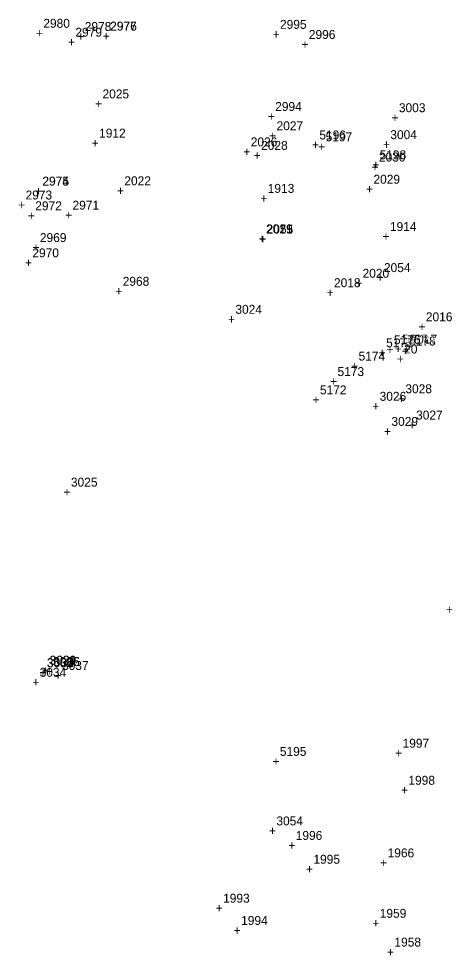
# Model space of a CAD drawing. Extents: x 1036751 to 1042192, y 772604 to 785439.
# Drawn here: x 1040862.7 to 1040984, y 774764.4 to 775026.4 of the extents above; entities that cross this region are included whole.
import ezdxf

# ---------------------------------------------------------------- set-up
doc = ezdxf.new("R2010")
doc.units = 0
for name, color, linetype in [('S_Control_Geodetic_ControlPoint', 7, 'Continuous'), ('S_Curb_Type_3', 7, 'Continuous'), ('S_Drainage_CB', 7, 'Continuous'), ('S_Drainage_Culvert_Top', 7, 'Continuous'), ('S_Drainage_Invert', 7, 'Continuous'), ('S_Drainage_Sump', 7, 'Continuous'), ('S_Fencing_Picket', 7, 'Continuous'), ('S_Ground_LevelString', 7, 'Continuous'), ('S_Property_IronPipeFound', 7, 'Continuous'), ('S_Property_Light', 7, 'Continuous'), ('S_Roadway_Centerline', 7, 'Continuous'), ('S_Roadway_Edge_Pavement', 7, 'Continuous'), ('S_Roadway_Edge_TW', 7, 'Continuous'), ('S_Traffic_Sign_DoublePost', 7, 'Continuous'), ('S_Traffic_Sign_SinglePost', 7, 'Continuous'), ('S_Trees_Decid_Pay', 7, 'Continuous'), ('S_Utilities_GuyWire3', 7, 'Continuous'), ('S_Utilities_Pole_Power', 7, 'Continuous')]:
    doc.layers.add(name, color=color, linetype=linetype)

msp = doc.modelspace()

# ---------------------------------------------------------------- texts
at = {"layer": 'S_Control_Geodetic_ControlPoint'}
for s, p in [('20', (1040970.51, 774932.71)), ('20', (1040970.51, 774932.71)), ('20', (1040970.51, 774932.71)), ('20', (1040970.51, 774932.71)), ('20', (1040970.51, 774932.71)), ('20', (1040970.51, 774932.71)), ('20', (1040970.51, 774932.71)), ('20', (1040970.51, 774932.71)), ('20', (1040970.51, 774932.71)), ('20', (1040970.51, 774932.71)), ('+', (1040968.45, 774929.96)), ('+', (1040968.45, 774929.96)), ('+', (1040968.45, 774929.96)), ('+', (1040968.45, 774929.96)), ('+', (1040968.45, 774929.96)), ('+', (1040968.45, 774929.96)), ('+', (1040968.45, 774929.96)), ('+', (1040968.45, 774929.96)), ('+', (1040968.45, 774929.96)), ('+', (1040968.45, 774929.96))]:
    msp.add_text(s, height=2.5, dxfattribs=at).set_placement(p)
at = {"layer": 'S_Curb_Type_3'}
for s, p in [('5196', (1040946.79, 774992.59)), ('5197', (1040948.54, 774992.08)), ('+', (1040944.73, 774989.84)), ('+', (1040946.48, 774989.33)), ('5198', (1040963.65, 774987.05)), ('+', (1040961.59, 774984.3)), ('5176', (1040967.65, 774935.32)), ('5177', (1040969.93, 774935.52)), ('5178', (1040971.91, 774934.94)), ('5175', (1040965.46, 774934.47)), ('+', (1040965.59, 774932.57)), ('+', (1040967.87, 774932.77)), ('5174', (1040957.76, 774930.74)), ('+', (1040963.4, 774931.72)), ('+', (1040969.85, 774932.19)), ('+', (1040955.7, 774927.99)), ('5173', (1040951.87, 774926.4)), ('+', (1040949.81, 774923.65)), ('5172', (1040946.95, 774921.28)), ('+', (1040944.89, 774918.53)), ('+', (1040982.18, 774859.93)), ('5195', (1040935.74, 774820.15)), ('+', (1040933.68, 774817.4))]:
    msp.add_text(s, height=2.5, dxfattribs=at).set_placement(p)
at = {"layer": 'S_Drainage_CB'}
for s, p in [('3030', (1040871.32, 774845.69)), ('+', (1040869.26, 774842.94))]:
    msp.add_text(s, height=2.5, dxfattribs=at).set_placement(p)
at = {"layer": 'S_Drainage_Culvert_Top'}
for s, p in [('2976', (1040888.3, 775023.03)), ('+', (1040886.24, 775020.28)), ('2975', (1040869.34, 774979.67)), ('+', (1040867.28, 774976.92)), ('3033', (1040870.57, 774844.91)), ('3036', (1040872.34, 774845.26)), ('3037', (1040874.81, 774844.18)), ('3034', (1040868.55, 774842.27)), ('+', (1040868.51, 774842.16)), ('+', (1040870.28, 774842.51)), ('+', (1040872.75, 774841.43)), ('+', (1040866.49, 774839.52))]:
    msp.add_text(s, height=2.5, dxfattribs=at).set_placement(p)
at = {"layer": 'S_Drainage_Invert'}
for s, p in [('2977', (1040888.25, 775023.06)), ('+', (1040886.19, 775020.31)), ('2974', (1040869.3, 774979.67)), ('+', (1040867.23, 774976.92)), ('3032', (1040870.59, 774844.98)), ('3035', (1040872.33, 774845.27)), ('+', (1040868.53, 774842.23)), ('+', (1040870.27, 774842.52))]:
    msp.add_text(s, height=2.5, dxfattribs=at).set_placement(p)
at = {"layer": 'S_Drainage_Sump'}
for s, p in [('3031', (1040871.32, 774845.64)), ('+', (1040869.25, 774842.89))]:
    msp.add_text(s, height=2.5, dxfattribs=at).set_placement(p)
at = {"layer": 'S_Fencing_Picket'}
for s, p in [('2980', (1040869.57, 775023.82)), ('2995', (1040935.78, 775023.53)), ('2979', (1040878.55, 775021.33)), ('+', (1040867.5, 775021.07)), ('+', (1040933.72, 775020.78)), ('2996', (1040943.85, 775020.7)), ('+', (1040876.49, 775018.58)), ('+', (1040941.79, 775017.95))]:
    msp.add_text(s, height=2.5, dxfattribs=at).set_placement(p)
at = {"layer": 'S_Ground_LevelString'}
for s, p in [('2055', (1040932.04, 774966.25)), ('+', (1040929.98, 774963.5)), ('2054', (1040964.86, 774955.48)), ('+', (1040962.8, 774952.73))]:
    msp.add_text(s, height=2.5, dxfattribs=at).set_placement(p)
at = {"layer": 'S_Property_IronPipeFound'}
for s, p in [('2978', (1040881.17, 775022.94)), ('+', (1040879.11, 775020.19)), ('3024', (1040923.3, 774943.81)), ('+', (1040921.24, 774941.06)), ('3025', (1040877.3, 774895.47)), ('+', (1040875.24, 774892.72))]:
    msp.add_text(s, height=2.5, dxfattribs=at).set_placement(p)
at = {"layer": 'S_Property_Light'}
for s, p in [('3026', (1040963.65, 774919.48)), ('+', (1040961.59, 774916.73)), ('3027', (1040973.85, 774914.24)), ('+', (1040971.79, 774911.49))]:
    msp.add_text(s, height=2.5, dxfattribs=at).set_placement(p)
at = {"layer": 'S_Roadway_Centerline'}
for s, p in [('1912', (1040885.18, 774993.11)), ('+', (1040883.12, 774990.36)), ('1913', (1040932.35, 774977.65)), ('+', (1040930.29, 774974.9)), ('1914', (1040966.53, 774966.96)), ('+', (1040964.47, 774964.21)), ('1966', (1040965.88, 774791.76)), ('+', (1040963.82, 774789.01))]:
    msp.add_text(s, height=2.5, dxfattribs=at).set_placement(p)
at = {"layer": 'S_Roadway_Edge_Pavement'}
for s, p in [('2025', (1040886.13, 775004.07)), ('+', (1040884.07, 775001.32)), ('2027', (1040934.82, 774995.16)), ('2026', (1040927.6, 774990.65)), ('+', (1040932.76, 774992.41)), ('+', (1040925.54, 774987.9)), ('2030', (1040963.45, 774986.4)), ('+', (1040961.39, 774983.65)), ('2022', (1040892.24, 774979.77)), ('+', (1040890.17, 774977.02)), ('2019', (1040931.88, 774966.33)), ('+', (1040929.82, 774963.58)), ('2018', (1040950.89, 774951.26)), ('+', (1040948.83, 774948.51)), ('2017', (1040972.29, 774935.48)), ('+', (1040970.23, 774932.73)), ('1997', (1040970.06, 774822.44)), ('+', (1040968, 774819.69)), ('1996', (1040940.19, 774796.65)), ('+', (1040938.13, 774793.9)), ('1993', (1040919.87, 774779.08)), ('+', (1040917.81, 774776.33)), ('1958', (1040967.79, 774766.81)), ('+', (1040965.73, 774764.06))]:
    msp.add_text(s, height=2.5, dxfattribs=at).set_placement(p)
at = {"layer": 'S_Roadway_Edge_TW'}
for s, p in [('2028', (1040930.5, 774989.67)), ('+', (1040928.44, 774986.92)), ('2029', (1040961.92, 774980.2)), ('+', (1040959.86, 774977.45)), ('2021', (1040931.88, 774966.35)), ('+', (1040929.82, 774963.6)), ('2020', (1040958.88, 774953.89)), ('+', (1040956.82, 774951.14)), ('2016', (1040976.58, 774941.72)), ('+', (1040974.52, 774938.97)), ('1998', (1040971.7, 774812.07)), ('+', (1040969.64, 774809.32)), ('1995', (1040945.14, 774789.98)), ('+', (1040943.08, 774787.23)), ('1959', (1040963.69, 774774.86)), ('1994', (1040924.91, 774772.86)), ('+', (1040922.84, 774770.11)), ('+', (1040961.62, 774772.11))]:
    msp.add_text(s, height=2.5, dxfattribs=at).set_placement(p)
at = {"layer": 'S_Traffic_Sign_DoublePost'}
for s, p in [('3003', (1040969.04, 775000.21)), ('+', (1040966.98, 774997.46)), ('3004', (1040966.64, 774992.67)), ('+', (1040964.58, 774989.92)), ('2969', (1040868.61, 774963.88)), ('+', (1040866.55, 774961.13)), ('2970', (1040866.51, 774959.61)), ('+', (1040864.45, 774956.86)), ('3028', (1040970.85, 774921.59)), ('+', (1040968.79, 774918.84)), ('3029', (1040966.95, 774912.46)), ('+', (1040964.89, 774909.71))]:
    msp.add_text(s, height=2.5, dxfattribs=at).set_placement(p)
at = {"layer": 'S_Traffic_Sign_SinglePost'}
for s, p in [('2973', (1040864.6, 774975.79)), ('+', (1040862.53, 774973.04))]:
    msp.add_text(s, height=2.5, dxfattribs=at).set_placement(p)
at = {"layer": 'S_Trees_Decid_Pay'}
for s, p in [('2968', (1040891.78, 774951.65)), ('+', (1040889.72, 774948.9))]:
    msp.add_text(s, height=2.5, dxfattribs=at).set_placement(p)
at = {"layer": 'S_Utilities_GuyWire3'}
for s, p in [('2972', (1040867.32, 774972.78)), ('+', (1040865.26, 774970.03))]:
    msp.add_text(s, height=2.5, dxfattribs=at).set_placement(p)
at = {"layer": 'S_Utilities_Pole_Power'}
for s, p in [('2994', (1040934.43, 775000.55)), ('+', (1040932.37, 774997.8)), ('2971', (1040877.74, 774972.95)), ('+', (1040875.68, 774970.2)), ('3054', (1040934.77, 774800.7)), ('+', (1040932.71, 774797.95))]:
    msp.add_text(s, height=2.5, dxfattribs=at).set_placement(p)

doc.saveas('drawing.dxf')
